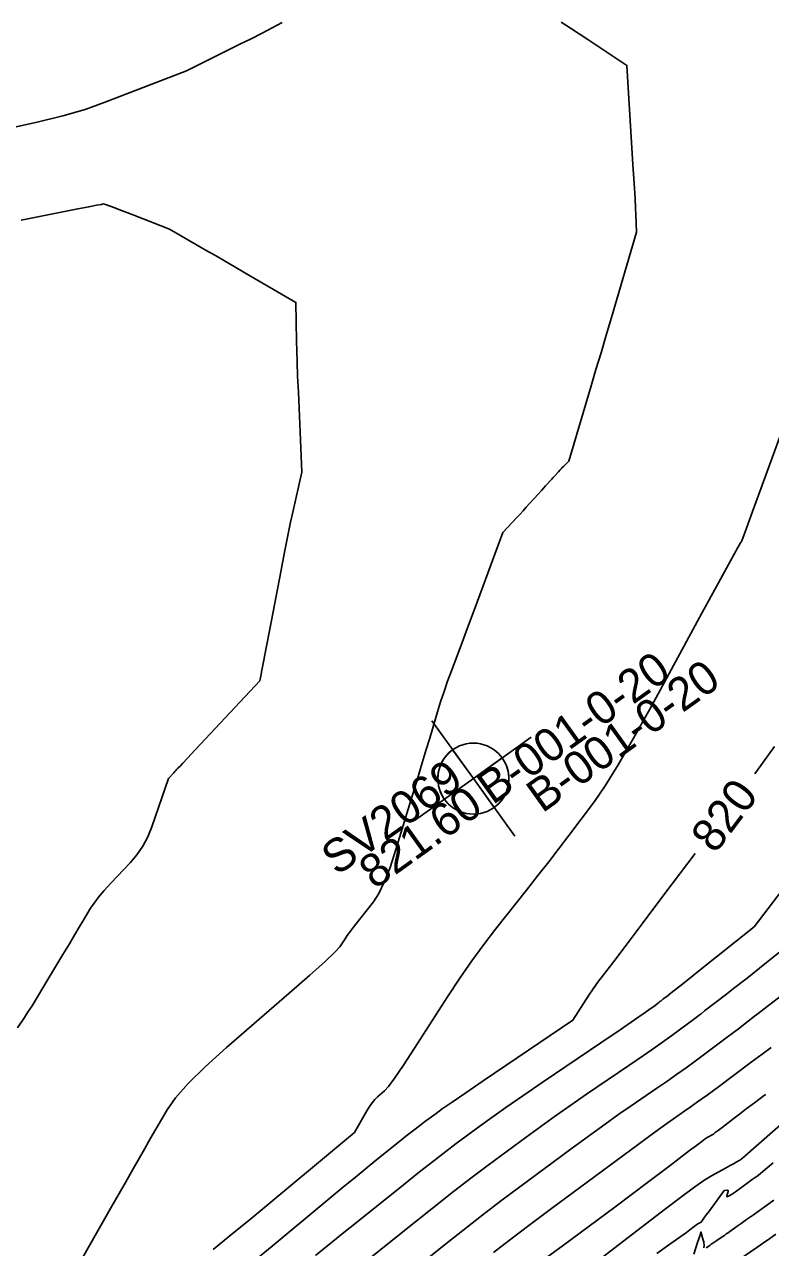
# Model space of a CAD drawing. Extents: x 2079879 to 2092887, y 778083 to 784051.
# Drawn here: x 2083962.9 to 2084025.9, y 780863.7 to 780967 of the extents above; entities that cross this region are included whole.
import ezdxf

# ---------------------------------------------------------------- set-up
doc = ezdxf.new("R2010")
doc.units = 0
for name, color, linetype in [('DT_X_Contour_Major', 7, 'Continuous'), ('DT_X_Contour_Minor', 7, 'Continuous'), ('GT_Project_Soil_Boring', 7, 'Continuous'), ('GT_Project_Text', 7, 'Continuous'), ('SV_X_Text_Comment', 7, 'Continuous'), ('SV_X_Text_Elevation', 7, 'Continuous'), ('SV_X_Text_Name', 7, 'Continuous')]:
    doc.layers.add(name, color=color, linetype=linetype)

msp = doc.modelspace()

# ---------------------------------------------------------------- linework, layer by layer
at = {"layer": 'DT_X_Contour_Major'}
for points in [[(2084026.28, 780906.05), (2084024.76, 780903.95), (2084024.62, 780903.75)], [(2084019.58, 780897.03), (2084017.02, 780893.63), (2084015.09, 780891.07), (2084013.65, 780889.16), (2084012.7, 780887.9), (2084012.23, 780887.29), (2084011.63, 780886.53), (2084011.4, 780886.23), (2084011.15, 780885.88), (2084010.89, 780885.49), (2084010.6, 780885.06), (2084009.24, 780882.95), (2084001.67, 780877.81), (2084000.2, 780876.81), (2083999.05, 780876.02), (2083998.21, 780875.44), (2083997.69, 780875.06), (2083996.71, 780874.34), (2083996.3, 780874.03), (2083995.82, 780873.66), (2083995.26, 780873.22), (2083994.63, 780872.72), (2083992.84, 780871.29), (2083992.05, 780870.64), (2083991.02, 780869.8), (2083989.74, 780868.74), (2083988.22, 780867.48), (2083983.84, 780863.84), (2083982.12, 780862.45)], [(2084025.53, 780876.67), (2084025.42, 780876.6), (2084024.58, 780875.97), (2084023.87, 780875.44), (2084023.3, 780875), (2084022.85, 780874.66), (2084021.84, 780873.88), (2084021.5, 780873.62), (2084021.26, 780873.44), (2084021.11, 780873.32), (2084021.05, 780873.28), (2084021.02, 780873.26), (2084021, 780873.25), (2084020.9, 780873.19), (2084020.82, 780873.15), (2084020.58, 780873.02), (2084020.42, 780872.91), (2084020.12, 780872.69), (2084019.67, 780872.36), (2084019.09, 780871.92), (2084017.34, 780870.57), (2084016.57, 780869.98), (2084015.55, 780869.22), (2084014.28, 780868.28), (2084012.78, 780867.16), (2084008.44, 780863.95), (2084006.98, 780862.86)]]:
    msp.add_lwpolyline(points, dxfattribs=at)
at = {"layer": 'DT_X_Contour_Minor'}
for points in [[(2083961.57, 780958.26), (2083964, 780958.78), (2083966.16, 780959.32), (2083968.05, 780959.87), (2083969.67, 780960.44), (2083976.62, 780963.14), (2083981.13, 780965.37), (2083982.08, 780965.84), (2083982.99, 780966.31), (2083983.86, 780966.76), (2083984.69, 780967.2)], [(2084008.26, 780967.24), (2084009.03, 780966.74), (2084009.78, 780966.25), (2084010.5, 780965.77), (2084013.8, 780963.59), (2084014.32, 780955.22), (2084014.42, 780953.61), (2084014.49, 780952.37), (2084014.54, 780951.49), (2084014.57, 780950.99), (2084014.62, 780949.49), (2084012.5, 780942.3), (2084012.05, 780940.79), (2084011.62, 780939.32), (2084011.19, 780937.89), (2084010.78, 780936.51), (2084008.9, 780930.17), (2084008.45, 780929.72), (2084008.35, 780929.62), (2084008.25, 780929.51), (2084008.14, 780929.39), (2084008.02, 780929.26), (2084007.69, 780928.9), (2084007.57, 780928.77), (2084007.47, 780928.65), (2084007.37, 780928.54), (2084007.05, 780928.19), (2084006.94, 780928.07), (2084006.78, 780927.9), (2084006.58, 780927.67), (2084006.33, 780927.39), (2084005.59, 780926.57), (2084005.31, 780926.26), (2084005.04, 780925.97), (2084004.78, 780925.68), (2084004.52, 780925.4), (2084003.34, 780924.12), (2084000.98, 780917.8), (2084000.59, 780916.76), (2084000.22, 780915.78), (2083999.88, 780914.85), (2083998.98, 780912.46), (2083998.66, 780911.57), (2083998.36, 780910.69), (2083998.07, 780909.83), (2083997.81, 780908.99), (2083997.15, 780906.75), (2083996.86, 780905.81), (2083996.52, 780904.67), (2083996.11, 780903.32), (2083995.64, 780901.77), (2083994.29, 780897.37), (2083993.8, 780895.85), (2083993.32, 780894.61), (2083992.85, 780893.64), (2083992.4, 780892.94), (2083991.21, 780891.44), (2083990.8, 780890.92), (2083990.46, 780890.47), (2083990.19, 780890.1), (2083990, 780889.81), (2083989.56, 780889.14), (2083989.17, 780888.71), (2083988.33, 780887.91), (2083987.03, 780886.74), (2083985.27, 780885.21), (2083979.99, 780880.63), (2083978.19, 780879.01), (2083976.75, 780877.59), (2083975.68, 780876.37), (2083974.97, 780875.36), (2083973.55, 780872.91), (2083972.95, 780871.86), (2083972.21, 780870.57), (2083971.34, 780869.03), (2083970.32, 780867.24), (2083965.25, 780858.31)], [(2083962.64, 780950.52), (2083967.45, 780951.47), (2083968.36, 780951.65), (2083969.02, 780951.78), (2083969.43, 780951.85), (2083969.59, 780951.88), (2083969.78, 780951.85), (2083970.55, 780951.56), (2083970.77, 780951.47), (2083971.12, 780951.34), (2083971.58, 780951.16), (2083972.17, 780950.93), (2083975.17, 780949.76), (2083978.34, 780947.93), (2083979.05, 780947.52), (2083979.82, 780947.08), (2083980.65, 780946.59), (2083981.54, 780946.07), (2083985.85, 780943.56), (2083985.91, 780940.29), (2083985.93, 780939.49), (2083985.96, 780938.51), (2083986, 780937.35), (2083986.06, 780935.99), (2083986.35, 780929.23), (2083985.59, 780925.86), (2083985.41, 780925.01), (2083985.17, 780923.88), (2083984.9, 780922.48), (2083984.57, 780920.8), (2083983.65, 780915.97), (2083983.34, 780914.38), (2083983.12, 780913.22), (2083982.98, 780912.49), (2083982.92, 780912.19), (2083982.88, 780911.98), (2083982.87, 780911.91), (2083982.85, 780911.84), (2083982.84, 780911.79), (2083982.84, 780911.76), (2083982.81, 780911.61), (2083978.22, 780906.7), (2083977.35, 780905.77), (2083976.71, 780905.08), (2083976.29, 780904.64), (2083976.1, 780904.43), (2083975.88, 780904.22), (2083975.8, 780904.13), (2083975.72, 780904.04), (2083975.63, 780903.95), (2083975.54, 780903.84), (2083975.1, 780903.36), (2083973.68, 780899.28), (2083973.34, 780898.44), (2083972.92, 780897.65), (2083972.42, 780896.91), (2083971.85, 780896.24), (2083970.23, 780894.51), (2083969.67, 780893.89), (2083969.19, 780893.34), (2083968.81, 780892.83), (2083968.52, 780892.39), (2083967.86, 780891.29), (2083967.56, 780890.81), (2083967.19, 780890.18), (2083966.72, 780889.4), (2083966.17, 780888.48), (2083964.57, 780885.82), (2083964.02, 780884.91), (2083963.57, 780884.16), (2083963.2, 780883.58), (2083962.93, 780883.17), (2083962.34, 780882.28)], [(2084027.25, 780933.69), (2084025.12, 780927.83), (2084024.42, 780925.9), (2084023.91, 780924.51), (2084023.59, 780923.66), (2084023.47, 780923.36), (2084023.4, 780923.27), (2084023.17, 780922.87), (2084022.56, 780921.75), (2084021.55, 780919.89), (2084020.14, 780917.31), (2084015.88, 780909.46), (2084014.37, 780906.75), (2084013.07, 780904.5), (2084011.97, 780902.73), (2084011.06, 780901.42), (2084008.9, 780898.55), (2084008.08, 780897.46), (2084007.2, 780896.32), (2084006.29, 780895.15), (2084005.33, 780893.93), (2084002.71, 780890.62), (2084001.73, 780889.33), (2084000.72, 780887.95), (2083999.7, 780886.48), (2083998.66, 780884.91), (2083995.88, 780880.59), (2083994.93, 780879.15), (2083994.2, 780878.07), (2083993.67, 780877.34), (2083993.34, 780876.97), (2083992.75, 780876.46), (2083992.53, 780876.24), (2083992.3, 780875.97), (2083992.08, 780875.66), (2083991.85, 780875.29), (2083990.79, 780873.45), (2083982.04, 780866.17), (2083980.31, 780864.74), (2083978.86, 780863.58)], [(2084032.18, 780900.82), (2084024.56, 780890.83), (2084019.86, 780887.07), (2084018.96, 780886.35), (2084018.27, 780885.81), (2084017.8, 780885.44), (2084017.55, 780885.24), (2084017.17, 780884.95), (2084017.04, 780884.85), (2084016.93, 780884.77), (2084016.85, 780884.71), (2084016.79, 780884.66), (2084016.67, 780884.56), (2084016.6, 780884.51), (2084016.5, 780884.43), (2084016.36, 780884.33), (2084016.18, 780884.19), (2084015.65, 780883.8), (2084015.25, 780883.52), (2084014.44, 780882.96), (2084013.23, 780882.13), (2084011.6, 780881.03), (2084006.73, 780877.72), (2084005.03, 780876.56), (2084003.59, 780875.56), (2084002.41, 780874.73), (2084001.49, 780874.07), (2083999.39, 780872.51), (2083998.52, 780871.85), (2083997.49, 780871.06), (2083996.3, 780870.12), (2083994.94, 780869.04), (2083991.11, 780865.97), (2083989.75, 780864.88), (2083988.55, 780863.9), (2083987.5, 780863.05)], [(2084027.78, 780889.56), (2084025.6, 780887.82), (2084023.95, 780886.5), (2084022.82, 780885.61), (2084022.21, 780885.13), (2084021.28, 780884.42), (2084020.96, 780884.18), (2084020.7, 780883.98), (2084020.5, 780883.83), (2084020.36, 780883.72), (2084020.07, 780883.48), (2084019.91, 780883.36), (2084019.66, 780883.17), (2084019.32, 780882.91), (2084018.89, 780882.59), (2084017.61, 780881.64), (2084017.02, 780881.21), (2084016.22, 780880.65), (2084015.2, 780879.95), (2084013.97, 780879.11), (2084010.4, 780876.68), (2084009.08, 780875.77), (2084007.78, 780874.87), (2084006.53, 780873.97), (2084005.3, 780873.07), (2084002.08, 780870.68), (2084000.75, 780869.68), (2083999.17, 780868.47), (2083997.36, 780867.04), (2083995.31, 780865.4), (2083989.5, 780860.75)], [(2084026.86, 780885.02), (2084025.39, 780883.89), (2084024.88, 780883.51), (2084024.47, 780883.19), (2084024.15, 780882.95), (2084023.93, 780882.77), (2084023.47, 780882.4), (2084023.22, 780882.21), (2084022.82, 780881.91), (2084022.28, 780881.5), (2084021.6, 780880.99), (2084019.57, 780879.48), (2084018.8, 780878.91), (2084018, 780878.34), (2084017.18, 780877.76), (2084016.34, 780877.19), (2084014.07, 780875.65), (2084013.12, 780874.99), (2084011.98, 780874.17), (2084010.64, 780873.2), (2084009.11, 780872.07), (2084004.76, 780868.85), (2084003.14, 780867.64), (2084001.53, 780866.41), (2083999.94, 780865.18), (2083998.37, 780863.93), (2083994.2, 780860.59)], [(2084025.99, 780880.64), (2084025.24, 780880.08), (2084024.3, 780879.38), (2084021.53, 780877.31), (2084020.57, 780876.6), (2084019.78, 780876.03), (2084019.16, 780875.58), (2084018.71, 780875.27), (2084017.74, 780874.61), (2084017.17, 780874.2), (2084016.17, 780873.48), (2084014.76, 780872.44), (2084012.92, 780871.08), (2084007.45, 780867.03), (2084005.53, 780865.6), (2084003.89, 780864.36), (2084002.53, 780863.32)], [(2084029.32, 780876.32), (2084023.58, 780871.28), (2084023.46, 780871.19), (2084023.43, 780871.17), (2084023.39, 780871.14), (2084023.35, 780871.11), (2084023.29, 780871.08), (2084023.03, 780870.94), (2084022.82, 780870.82), (2084022.53, 780870.66), (2084022.13, 780870.45), (2084020.96, 780869.8), (2084020.38, 780869.45), (2084019.55, 780868.86), (2084018.44, 780868.05), (2084017.07, 780867.01), (2084013.07, 780863.94), (2084011.71, 780862.9)], [(2084026.16, 780870.88), (2084025.49, 780870.32), (2084025.08, 780869.98), (2084024.93, 780869.86), (2084024.88, 780869.82), (2084024.81, 780869.77), (2084024.65, 780869.65), (2084024.39, 780869.47), (2084024.04, 780869.22), (2084022.97, 780868.45), (2084022.63, 780868.21), (2084022.39, 780868.07), (2084022.26, 780868.03), (2084022.24, 780868.09), (2084022.33, 780868.38), (2084022.35, 780868.47), (2084022.35, 780868.54), (2084022.33, 780868.57), (2084022.29, 780868.58), (2084022.02, 780868.54), (2084020.78, 780866.85), (2084020.54, 780866.53), (2084020.36, 780866.29), (2084020.25, 780866.13), (2084020.19, 780866.06), (2084020.07, 780865.89), (2084019.85, 780865.77), (2084019.79, 780865.73), (2084019.71, 780865.68), (2084019.6, 780865.6), (2084019.48, 780865.5), (2084019.11, 780865.22), (2084018.83, 780865.01), (2084018.27, 780864.61), (2084017.43, 780864.02), (2084016.32, 780863.23)], [(2084026.2, 780867.75), (2084024.49, 780866.51), (2084023.9, 780866.1), (2084023.45, 780865.77), (2084023.11, 780865.53), (2084022.9, 780865.38), (2084022.51, 780865.1), (2084022.36, 780864.99), (2084022.2, 780864.88), (2084022.04, 780864.76), (2084021.86, 780864.65), (2084021.39, 780864.32), (2084021.22, 780864.21), (2084021.06, 780864.1), (2084020.93, 780864.01), (2084020.8, 780863.92), (2084020.5, 780863.72)], [(2084020.3, 780863.71), (2084020.32, 780863.92), (2084020.32, 780864), (2084020.31, 780864.11), (2084020.29, 780864.23), (2084020.25, 780864.36), (2084020.06, 780865.05), (2084020.03, 780864.94), (2084020.01, 780864.87), (2084019.96, 780864.72), (2084019.88, 780864.48), (2084019.77, 780864.15), (2084019.45, 780863.18)], [(2084026.38, 780864.86), (2084025.87, 780864.5), (2084025.34, 780864.13), (2084024.78, 780863.75), (2084023.25, 780862.71)]]:
    msp.add_lwpolyline(points, dxfattribs=at)
at = {"layer": 'GT_Project_Soil_Boring'}
for p, q in [((2084000.84, 780903.34), (2083997.34, 780908.22)), ((2084000.84, 780903.34), (2084005.72, 780906.84)), ((2083999.09, 780905.78), (2084000.84, 780903.34)), ((2084000.84, 780903.34), (2084003.28, 780905.09)), ((2084000.84, 780903.34), (2083995.96, 780899.85)), ((2084000.84, 780903.34), (2083998.4, 780901.6)), ((2084000.84, 780903.34), (2084004.33, 780898.47)), ((2084002.59, 780900.91), (2084000.84, 780903.34))]:
    msp.add_line(p, q, dxfattribs=at)
msp.add_circle((2084000.84, 780903.34), 3, dxfattribs=at)
for start, end in [(125.6254, 215.6254), (305.6254, 35.6254)]:
    msp.add_arc((2084000.84, 780903.34), 3, start, end, dxfattribs=at)

# ---------------------------------------------------------------- texts
at = {"layer": 'DT_X_Contour_Major'}
msp.add_text('820', height=2.8, rotation=53.1534, dxfattribs=at).set_placement((2084021.26, 780896.92))
at = {"layer": 'GT_Project_Text'}
msp.add_text('B-001-0-20', height=2.8, rotation=35.6254, dxfattribs=at).set_placement((2084006.66, 780900.38))
at = {"layer": 'SV_X_Text_Comment'}
msp.add_text('B-001-0-20', height=2.8, rotation=35.6254, dxfattribs=at).set_placement((2084002.47, 780901.07))
at = {"layer": 'SV_X_Text_Elevation'}
msp.add_text('821.60', height=2.8, rotation=35.6254, dxfattribs=at).set_placement((2083992.51, 780893.93))
at = {"layer": 'SV_X_Text_Name'}
msp.add_text('SV2069', height=2.8, rotation=35.6254, dxfattribs=at).set_placement((2083989.32, 780895.09))

doc.saveas('drawing.dxf')
